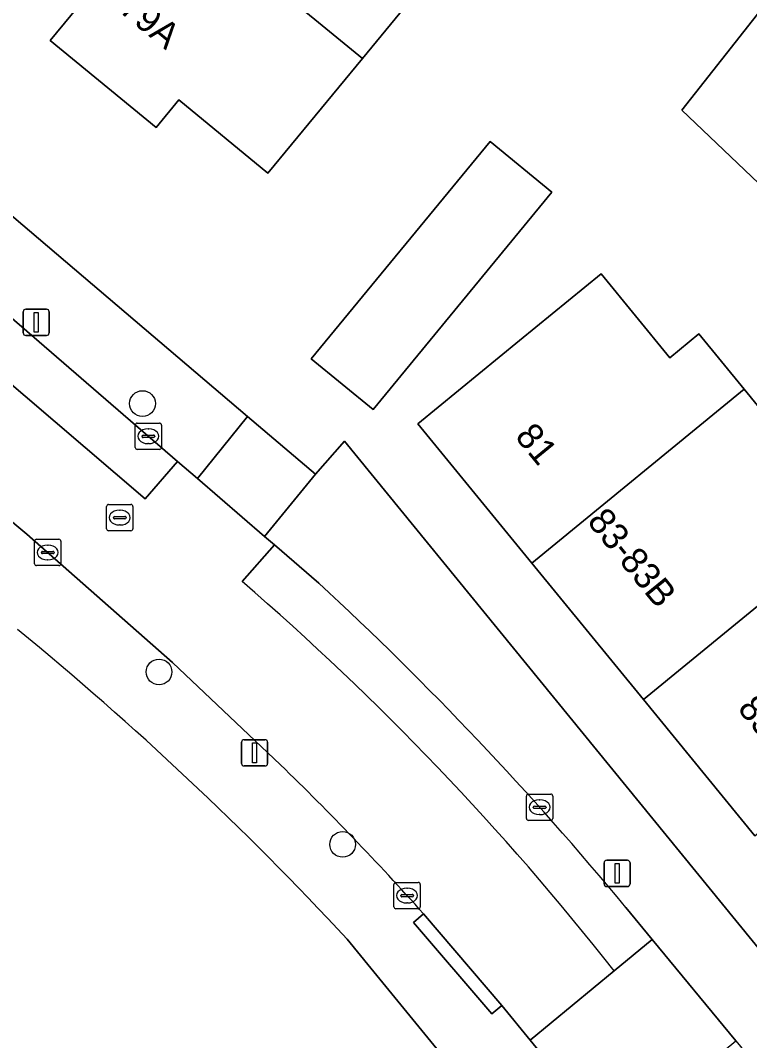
# Model space of a CAD drawing. Extents: x 162073 to 163043, y 381818 to 382561.
# Drawn here: x 162574.72 to 162602.44, y 382030.78 to 382069.57 of the extents above; entities that cross this region are included whole.
import ezdxf

# ---------------------------------------------------------------- set-up
doc = ezdxf.new("R2010")
doc.units = 0
for name, color, linetype in [('IMGEO_Boom', 7, 'Continuous'), ('IMGEO_Erf', 7, 'Continuous'), ('IMGEO_Kolk', 7, 'Continuous'), ('IMGEO_Lichtmast', 7, 'Continuous'), ('IMGEO_Pand', 7, 'Continuous'), ('IMGEO_Pand_nummerreeks', 7, 'Continuous'), ('IMGEO_Parkeervlak_open', 7, 'Continuous'), ('IMGEO_Rijbaan_lokaal_open', 7, 'Continuous'), ('IMGEO_Rioolput', 7, 'Continuous'), ('IMGEO_Voetpad_open', 7, 'Continuous')]:
    doc.layers.add(name, color=color, linetype=linetype)

msp = doc.modelspace()

# ---------------------------------------------------------------- linework, layer by layer
at = {"layer": 'IMGEO_Boom'}
for centre in [(162579.361, 382055), (162579.99, 382044.797), (162586.969, 382038.24)]:
    msp.add_circle(centre, 0.489, dxfattribs=at)
at = {"layer": 'IMGEO_Erf'}
for points in [[(162610.06, 382116.173), (162569.158, 382066.59), (162583.359, 382054.51), (162585.935, 382052.319), (162587.039, 382053.571), (162630.776, 382000)], [(162591.216, 382072.366), (162587.721, 382068.121), (162584.131, 382063.76), (162580.744, 382066.547), (162579.876, 382065.493), (162575.851, 382068.806), (162577.972, 382071.383)], [(162610.744, 382055.796), (162599.864, 382066.158), (162604.252, 382071.737)], [(162602.645, 382038.567), (162598.403, 382043.751), (162594.161, 382048.936), (162589.824, 382054.236), (162593.694, 382057.403), (162596.793, 382059.939), (162599.407, 382056.745), (162600.515, 382057.652), (162602.239, 382055.546), (162603.927, 382053.483)], [(162625.783, 381978.273), (162640.017, 381960.503), (162633.898, 381955.497), (162633.564, 381955.907), (162630.873, 381953.706), (162633.469, 381950.533), (162608.939, 381930.467), (162613.031, 381925.508), (162651.329, 381956.438), (162649.444, 381958.748), (162645.097, 381964.078), (162641.189, 381960.887), (162631.472, 381972.686), (162632.164, 381973.299), (162630.277, 381975.619), (162633.474, 381978.122), (162618.994, 381995.786), (162616.559, 381998.757), (162591.809, 382028.937), (162588.037, 382033.537), (162587.138, 382034.641)]]:
    msp.add_lwpolyline(points, dxfattribs=at)
msp.add_lwpolyline([(162588.125, 382054.77), (162585.775, 382056.705), (162592.579, 382064.97), (162594.929, 382063.036)], close=True, dxfattribs=at)
msp.add_arc((162494.336, 381948.449), 126.654, 42.88512, 50.66569, dxfattribs=at)
at = {"layer": 'IMGEO_Kolk'}
for p, q in [((162579.158, 382054.258), (162580.01, 382054.258)), ((162579.083, 382053.332), (162579.083, 382054.184)), ((162579.571, 382054.038), (162579.596, 382054.038)), ((162580.084, 382054.184), (162580.084, 382053.332)), ((162579.342, 382053.752), (162579.342, 382053.764)), ((162579.78, 382053.715), (162579.382, 382053.715)), ((162579.385, 382053.801), (162579.783, 382053.801)), ((162579.594, 382053.478), (162579.569, 382053.478)), ((162579.826, 382053.764), (162579.826, 382053.752)), ((162580.01, 382053.258), (162579.158, 382053.258)), ((162575.257, 382048.913), (162575.257, 382049.765)), ((162575.332, 382049.839), (162576.184, 382049.839)), ((162575.745, 382049.619), (162575.77, 382049.619)), ((162576.258, 382049.765), (162576.258, 382048.913)), ((162575.516, 382049.333), (162575.516, 382049.345)), ((162575.954, 382049.296), (162575.556, 382049.296)), ((162575.559, 382049.382), (162575.957, 382049.382)), ((162576, 382049.345), (162576, 382049.333)), ((162576.184, 382048.839), (162575.332, 382048.839)), ((162575.768, 382049.059), (162575.743, 382049.059)), ((162593.959, 382039.227), (162593.959, 382040.079)), ((162594.034, 382040.153), (162594.886, 382040.153)), ((162594.447, 382039.933), (162594.472, 382039.933)), ((162594.96, 382040.079), (162594.96, 382039.227)), ((162594.218, 382039.647), (162594.218, 382039.659)), ((162594.656, 382039.61), (162594.258, 382039.61)), ((162594.261, 382039.696), (162594.659, 382039.696)), ((162594.702, 382039.659), (162594.702, 382039.647)), ((162594.886, 382039.153), (162594.034, 382039.153)), ((162594.47, 382039.373), (162594.445, 382039.373)), ((162588.995, 382036.794), (162589.847, 382036.794)), ((162588.92, 382035.868), (162588.92, 382036.72)), ((162589.408, 382036.574), (162589.433, 382036.574)), ((162589.921, 382036.72), (162589.921, 382035.868)), ((162589.179, 382036.288), (162589.179, 382036.3)), ((162589.617, 382036.251), (162589.219, 382036.251)), ((162589.222, 382036.337), (162589.62, 382036.337)), ((162589.431, 382036.014), (162589.406, 382036.014)), ((162589.663, 382036.3), (162589.663, 382036.288)), ((162589.847, 382035.794), (162588.995, 382035.794))]:
    msp.add_line(p, q, dxfattribs=at)
for points in [[(162579.158, 382054.258), (162580.01, 382054.258)], [(162579.083, 382053.332), (162579.083, 382054.184)], [(162580.084, 382054.184), (162580.084, 382053.332)], [(162580.01, 382053.258), (162579.158, 382053.258)], [(162575.257, 382048.913), (162575.257, 382049.765)], [(162575.332, 382049.839), (162576.184, 382049.839)], [(162576.258, 382049.765), (162576.258, 382048.913)], [(162576.184, 382048.839), (162575.332, 382048.839)], [(162593.959, 382039.227), (162593.959, 382040.079)], [(162594.034, 382040.153), (162594.886, 382040.153)], [(162594.96, 382040.079), (162594.96, 382039.227)], [(162594.886, 382039.153), (162594.034, 382039.153)], [(162588.995, 382036.794), (162589.847, 382036.794)], [(162588.92, 382035.868), (162588.92, 382036.72)], [(162589.921, 382036.72), (162589.921, 382035.868)], [(162589.847, 382035.794), (162588.995, 382035.794)]]:
    msp.add_lwpolyline(points, dxfattribs=at)
for centre, radius, start, end in [((162579.16, 382054.182), 0.0765, 91.552, 178.448), ((162579.16, 382054.182), 0.0765, 91.552, 178.448), ((162580.008, 382054.182), 0.0765, 1.552, 88.448), ((162580.008, 382054.182), 0.0765, 1.552, 88.448), ((162579.382, 382053.761), 0.0403, 85.8775, 175.7526), ((162579.379, 382053.751), 0.0366, 178.938, 274.7102), ((162579.783, 382053.758), 0.043, 264.8664, 352.4533), ((162579.787, 382053.763), 0.0386, 1.7309, 96.639), ((162579.16, 382053.334), 0.0765, 181.552, 268.448), ((162579.16, 382053.334), 0.0765, 181.552, 268.448), ((162580.008, 382053.334), 0.0765, 271.552, 358.448), ((162580.008, 382053.334), 0.0765, 271.552, 358.448), ((162575.334, 382049.763), 0.0765, 91.552, 178.448), ((162575.334, 382049.763), 0.0765, 91.552, 178.448), ((162576.182, 382049.763), 0.0765, 1.552, 88.448), ((162576.182, 382049.763), 0.0765, 1.552, 88.448), ((162575.556, 382049.342), 0.0403, 85.8775, 175.7526), ((162575.553, 382049.332), 0.0366, 178.938, 274.7102), ((162575.957, 382049.339), 0.043, 264.8664, 352.4533), ((162575.961, 382049.344), 0.0386, 1.7309, 96.639), ((162575.334, 382048.915), 0.0765, 181.552, 268.448), ((162575.334, 382048.915), 0.0765, 181.552, 268.448), ((162576.182, 382048.915), 0.0765, 271.552, 358.448), ((162576.182, 382048.915), 0.0765, 271.552, 358.448), ((162594.036, 382040.077), 0.0765, 91.552, 178.448), ((162594.036, 382040.077), 0.0765, 91.552, 178.448), ((162594.884, 382040.077), 0.0765, 1.552, 88.448), ((162594.884, 382040.077), 0.0765, 1.552, 88.448), ((162594.258, 382039.656), 0.0403, 85.8775, 175.7526), ((162594.255, 382039.646), 0.0366, 178.938, 274.7102), ((162594.659, 382039.653), 0.043, 264.8664, 352.4533), ((162594.663, 382039.658), 0.0386, 1.7309, 96.639), ((162594.036, 382039.229), 0.0765, 181.552, 268.448), ((162594.036, 382039.229), 0.0765, 181.552, 268.448), ((162594.884, 382039.229), 0.0765, 271.552, 358.448), ((162594.884, 382039.229), 0.0765, 271.552, 358.448), ((162588.997, 382036.718), 0.0765, 91.552, 178.448), ((162588.997, 382036.718), 0.0765, 91.552, 178.448), ((162589.845, 382036.718), 0.0765, 1.552, 88.448), ((162589.845, 382036.718), 0.0765, 1.552, 88.448), ((162589.219, 382036.297), 0.0403, 85.8775, 175.7526), ((162589.216, 382036.287), 0.0366, 178.938, 274.7102), ((162589.62, 382036.294), 0.043, 264.8664, 352.4533), ((162589.624, 382036.299), 0.0386, 1.7309, 96.639), ((162588.997, 382035.87), 0.0765, 181.552, 268.448), ((162588.997, 382035.87), 0.0765, 181.552, 268.448), ((162589.845, 382035.87), 0.0765, 271.552, 358.448), ((162589.845, 382035.87), 0.0765, 271.552, 358.448)]:
    msp.add_arc(centre, radius, start, end, dxfattribs=at)
for centre, major_axis, ratio, start_param, end_param in [((162579.57, 382053.758), (-0.387, 0.002), 0.722429, 4.712389, 7.853982), ((162579.595, 382053.758), (-0.39, 0.002), 0.717154, 1.570796, 4.712389), ((162575.744, 382049.339), (-0.387, 0.002), 0.722429, 4.712389, 7.853982), ((162575.769, 382049.339), (-0.39, 0.002), 0.717154, 1.570796, 4.712389), ((162594.446, 382039.653), (-0.387, 0.002), 0.722429, 4.712389, 7.853982), ((162594.471, 382039.653), (-0.39, 0.002), 0.717154, 1.570796, 4.712389), ((162589.407, 382036.294), (-0.387, 0.002), 0.722429, 4.712389, 7.853982), ((162589.432, 382036.294), (-0.39, 0.002), 0.717154, 1.570796, 4.712389)]:
    msp.add_ellipse(centre, major_axis=major_axis, ratio=ratio, start_param=start_param, end_param=end_param, dxfattribs=at)
at = {"layer": 'IMGEO_Lichtmast'}
for p, q in [((162574.823, 382057.691), (162574.823, 382058.491)), ((162574.823, 382058.491), (162574.823, 382057.691)), ((162574.923, 382058.591), (162575.713, 382058.591)), ((162575.713, 382058.591), (162574.923, 382058.591)), ((162575.813, 382058.491), (162575.813, 382057.691)), ((162575.813, 382057.691), (162575.813, 382058.491)), ((162575.713, 382057.591), (162574.923, 382057.591)), ((162574.923, 382057.591), (162575.713, 382057.591)), ((162583.226, 382042.221), (162584.016, 382042.221)), ((162584.016, 382042.221), (162583.226, 382042.221)), ((162583.126, 382041.321), (162583.126, 382042.121)), ((162583.126, 382042.121), (162583.126, 382041.321)), ((162584.116, 382042.121), (162584.116, 382041.321)), ((162584.116, 382041.321), (162584.116, 382042.121)), ((162584.016, 382041.221), (162583.226, 382041.221)), ((162583.226, 382041.221), (162584.016, 382041.221)), ((162597.009, 382037.636), (162597.799, 382037.636)), ((162597.799, 382037.636), (162597.009, 382037.636)), ((162596.909, 382036.736), (162596.909, 382037.536)), ((162596.909, 382037.536), (162596.909, 382036.736)), ((162597.899, 382037.536), (162597.899, 382036.736)), ((162597.899, 382036.736), (162597.899, 382037.536)), ((162597.799, 382036.636), (162597.009, 382036.636)), ((162597.009, 382036.636), (162597.799, 382036.636))]:
    msp.add_line(p, q, dxfattribs=at)
for points in [[(162575.243, 382058.466), (162575.393, 382058.466), (162575.393, 382057.716), (162575.243, 382057.716), (162575.243, 382058.466)], [(162583.546, 382042.096), (162583.696, 382042.096), (162583.696, 382041.346), (162583.546, 382041.346), (162583.546, 382042.096)], [(162597.329, 382037.511), (162597.479, 382037.511), (162597.479, 382036.761), (162597.329, 382036.761), (162597.329, 382037.511)]]:
    msp.add_lwpolyline(points, dxfattribs=at)
for centre, start, end in [((162574.923, 382058.491), 90, 180), ((162574.923, 382058.491), 90, 180), ((162575.713, 382058.491), 0, 90), ((162575.713, 382058.491), 360, 90), ((162574.923, 382057.691), 180, 270), ((162574.923, 382057.691), 180, 270), ((162575.713, 382057.691), 270, 0), ((162575.713, 382057.691), 270, 0), ((162583.226, 382042.121), 90, 180), ((162583.226, 382042.121), 90, 180), ((162584.016, 382042.121), 0, 90), ((162584.016, 382042.121), 360, 90), ((162583.226, 382041.321), 180, 270), ((162583.226, 382041.321), 180, 270), ((162584.016, 382041.321), 270, 0), ((162584.016, 382041.321), 270, 0), ((162597.009, 382037.536), 90, 180), ((162597.009, 382037.536), 90, 180), ((162597.799, 382037.536), 0, 90), ((162597.799, 382037.536), 360, 90), ((162597.009, 382036.736), 180, 270), ((162597.009, 382036.736), 180, 270), ((162597.799, 382036.736), 270, 0), ((162597.799, 382036.736), 270, 0)]:
    msp.add_arc(centre, 0.1, start, end, dxfattribs=at)
at = {"layer": 'IMGEO_Pand'}
for points in [[(162582.19, 382074.771), (162584.929, 382072.517), (162583.899, 382071.266), (162587.721, 382068.121), (162591.216, 382072.366), (162587.395, 382075.513), (162588.424, 382076.763), (162585.685, 382079.017)], [(162582.19, 382074.771), (162578.824, 382070.682), (162577.972, 382071.383), (162575.851, 382068.806), (162579.876, 382065.493), (162580.744, 382066.547), (162584.131, 382063.76), (162587.721, 382068.121), (162583.899, 382071.266), (162584.929, 382072.517)], [(162588.125, 382054.77), (162594.929, 382063.036), (162592.579, 382064.97), (162585.775, 382056.705)], [(162602.239, 382055.546), (162600.515, 382057.652), (162599.407, 382056.745), (162596.793, 382059.939), (162593.694, 382057.403), (162589.824, 382054.236), (162594.161, 382048.936)], [(162602.239, 382055.546), (162594.161, 382048.936), (162598.403, 382043.751), (162605.404, 382049.48), (162602.85, 382052.601), (162603.927, 382053.483)], [(162605.404, 382049.48), (162598.403, 382043.751), (162602.645, 382038.567), (162610.736, 382045.188), (162608.987, 382047.325), (162607.897, 382046.433)]]:
    msp.add_lwpolyline(points, close=True, dxfattribs=at)
at = {"layer": 'IMGEO_Parkeervlak_open'}
for points in [[(162568.044, 382061.134), (162579.468, 382051.383), (162580.692, 382052.802), (162571.751, 382060.51)], [(162586.065, 382048.171), (162584.378, 382049.625), (162583.153, 382048.232)], [(162597.293, 382033.427), (162598.742, 382034.623), (162597.741, 382035.836)]]:
    msp.add_lwpolyline(points, dxfattribs=at)
for centre, radius, start, end in [((162514.002, 381968.032), 105.896, 38.13679, 49.23098), ((162500.704, 381955.677), 125.864, 39.55904, 47.2967)]:
    msp.add_arc(centre, radius, start, end, dxfattribs=at)
at = {"layer": 'IMGEO_Rijbaan_lokaal_open'}
for points in [[(162526.502, 382090.663), (162528.495, 382088.989), (162536.729, 382082.148), (162544.264, 382075.847), (162553.211, 382068.229), (162560.822, 382061.89), (162571.093, 382053.249), (162574.964, 382050.041), (162580.499, 382045.158), (162584.603, 382041.27)], [(162604.252, 382071.737), (162599.864, 382066.158), (162610.744, 382055.796)], [(162583.153, 382048.232), (162584.378, 382049.625), (162584.003, 382049.948), (162581.447, 382052.151), (162580.692, 382052.802), (162579.468, 382051.383), (162568.044, 382061.134), (162564.146, 382064.364)], [(162590.05, 382035.597), (162593.025, 382032.116), (162594.105, 382030.795), (162597.293, 382033.427)]]:
    msp.add_lwpolyline(points, dxfattribs=at)
msp.add_lwpolyline([(162598.742, 382034.623), (162597.293, 382033.427), (162594.105, 382030.795), (162597.268, 382026.923), (162601.922, 382030.766)], close=True, dxfattribs=at)
for centre, radius, start, end in [((162514.002, 381968.032), 105.896, 38.13679, 49.23098), ((162509.277, 381963.494), 108.273, 41.75434, 45.91705)]:
    msp.add_arc(centre, radius, start, end, dxfattribs=at)
at = {"layer": 'IMGEO_Rioolput'}
for p, q in [((162578.07, 382051.164), (162578.922, 382051.164)), ((162577.995, 382050.238), (162577.995, 382051.09)), ((162578.483, 382050.944), (162578.508, 382050.944)), ((162578.996, 382051.09), (162578.996, 382050.238)), ((162578.254, 382050.658), (162578.254, 382050.67)), ((162578.692, 382050.621), (162578.294, 382050.621)), ((162578.297, 382050.707), (162578.695, 382050.707)), ((162578.506, 382050.384), (162578.481, 382050.384)), ((162578.738, 382050.67), (162578.738, 382050.658)), ((162578.922, 382050.164), (162578.07, 382050.164))]:
    msp.add_line(p, q, dxfattribs=at)
for points in [[(162578.07, 382051.164), (162578.922, 382051.164)], [(162577.995, 382050.238), (162577.995, 382051.09)], [(162578.996, 382051.09), (162578.996, 382050.238)], [(162578.922, 382050.164), (162578.07, 382050.164)]]:
    msp.add_lwpolyline(points, dxfattribs=at)
for centre, radius, start, end in [((162578.072, 382051.088), 0.0765, 91.552, 178.448), ((162578.072, 382051.088), 0.0765, 91.552, 178.448), ((162578.92, 382051.088), 0.0765, 1.552, 88.448), ((162578.92, 382051.088), 0.0765, 1.552, 88.448), ((162578.294, 382050.667), 0.0403, 85.8775, 175.7526), ((162578.291, 382050.657), 0.0366, 178.938, 274.7102), ((162578.695, 382050.664), 0.043, 264.8664, 352.4533), ((162578.699, 382050.669), 0.0386, 1.7309, 96.639), ((162578.072, 382050.24), 0.0765, 181.552, 268.448), ((162578.072, 382050.24), 0.0765, 181.552, 268.448), ((162578.92, 382050.24), 0.0765, 271.552, 358.448), ((162578.92, 382050.24), 0.0765, 271.552, 358.448)]:
    msp.add_arc(centre, radius, start, end, dxfattribs=at)
for centre, major_axis, ratio, start_param, end_param in [((162578.482, 382050.664), (-0.387, 0.002), 0.722429, 4.712389, 7.853982), ((162578.507, 382050.664), (-0.39, 0.002), 0.717154, 1.570796, 4.712389)]:
    msp.add_ellipse(centre, major_axis=major_axis, ratio=ratio, start_param=start_param, end_param=end_param, dxfattribs=at)
at = {"layer": 'IMGEO_Voetpad_open'}
for points in [[(162584.603, 382041.27), (162580.499, 382045.158), (162574.964, 382050.041), (162571.093, 382053.249), (162560.822, 382061.89), (162553.211, 382068.229), (162544.264, 382075.847), (162536.729, 382082.148), (162528.495, 382088.989), (162526.502, 382090.663)], [(162571.751, 382060.51), (162580.692, 382052.802), (162581.447, 382052.151), (162583.359, 382054.51), (162569.158, 382066.59)], [(162646.747, 381980.522), (162641.295, 381987.116), (162638.855, 381990.105), (162630.776, 382000), (162587.039, 382053.571), (162585.935, 382052.319), (162584.003, 382049.948), (162584.378, 382049.625), (162586.065, 382048.171)], [(162597.741, 382035.836), (162598.742, 382034.623), (162601.922, 382030.766), (162604.279, 382027.908), (162607.44, 382024.075), (162618.724, 382010.331), (162619.994, 382008.784), (162621.891, 382006.462), (162623.723, 382004.219), (162628.1, 381998.966), (162628.239, 381998.796)], [(162648.612, 381964.53), (162643.345, 381970.833), (162642.476, 381970.081), (162639.826, 381973.372), (162640.64, 381974.07), (162640.48, 381974.261), (162627.42, 381990.159), (162619.379, 382000), (162617.368, 382002.476), (162616.983, 382002.159), (162613.753, 382006.08), (162614.144, 382006.402), (162606.791, 382015.289), (162597.614, 382026.5), (162597.268, 382026.923), (162594.105, 382030.795), (162593.025, 382032.116), (162592.645, 382031.792), (162589.67, 382035.273), (162590.05, 382035.597)], [(162587.138, 382034.641), (162588.037, 382033.537), (162591.809, 382028.937), (162616.559, 381998.757), (162618.994, 381995.786), (162633.474, 381978.122), (162630.277, 381975.619), (162632.164, 381973.299), (162635.369, 381975.951), (162645.097, 381964.078), (162649.444, 381958.748), (162651.92, 381960.627), (162651.367, 381961.278), (162648.612, 381964.53)]]:
    msp.add_lwpolyline(points, dxfattribs=at)
for points in [[(162584.003, 382049.948), (162585.935, 382052.319), (162583.359, 382054.51), (162581.447, 382052.151)], [(162590.05, 382035.597), (162589.67, 382035.273), (162592.645, 382031.792), (162593.025, 382032.116)]]:
    msp.add_lwpolyline(points, close=True, dxfattribs=at)
for centre, radius, start, end in [((162500.704, 381955.677), 125.864, 39.55904, 47.2967), ((162494.336, 381948.449), 126.654, 42.88512, 50.66569), ((162509.277, 381963.494), 108.273, 41.75434, 45.91705)]:
    msp.add_arc(centre, radius, start, end, dxfattribs=at)

# ---------------------------------------------------------------- texts
at = {"layer": 'IMGEO_Pand_nummerreeks'}
for s, rotation, p in [('79A', 320.673, (162578.416, 382069.931)), ('81', 309.2935, (162593.491, 382053.734)), ('83-83B', 309.114, (162596.236, 382050.508)), ('85', 309.2907, (162601.952, 382043.395))]:
    msp.add_text(s, height=1, rotation=rotation, dxfattribs=at).set_placement(p)

doc.saveas('drawing.dxf')
